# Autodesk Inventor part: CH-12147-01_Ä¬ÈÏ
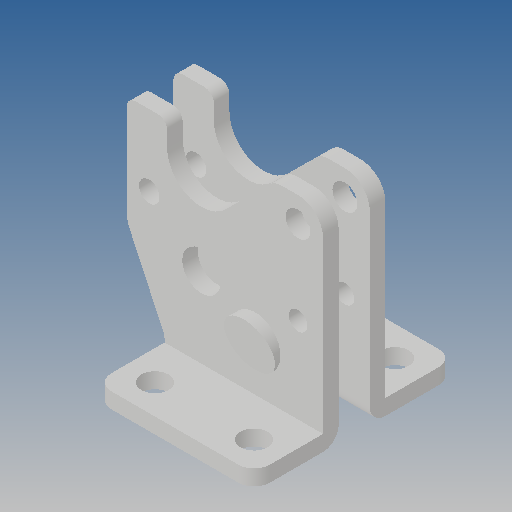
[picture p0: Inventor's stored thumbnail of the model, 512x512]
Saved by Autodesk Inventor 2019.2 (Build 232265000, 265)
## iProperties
Created: 2010-06
Part Number: CH-12147-01_Ä¬ÈÏ
Material: Ogólny
Document SubType Name: Modeling
Designer: CADENGINEERING4
Density: 1 g/cm^3
Appearance: Domyślna
Author: CADENGINEERING4
Revision Number: ÈÎºÎ
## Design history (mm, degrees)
feature "NONE"
feature "NONE:1"
node "Bryła1"
node "Bryła2"
